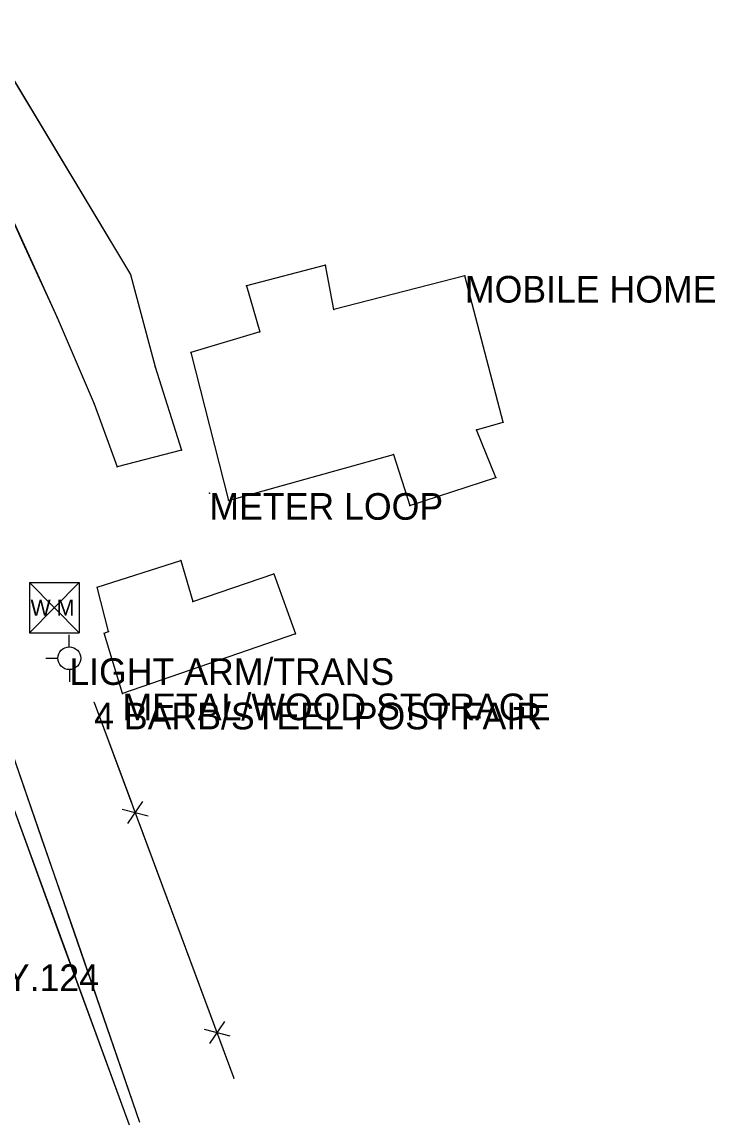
# Model space of a CAD drawing. Extents: x 1050807 to 1053552, y 395828 to 398415.
# Drawn here: x 1052790.6 to 1052920.5, y 395828.1 to 396034.9 of the extents above; entities that cross this region are included whole.
import ezdxf

# ---------------------------------------------------------------- set-up
doc = ezdxf.new("R2010")
doc.units = 0
for name, color, linetype in [('S_BREAKLINE_ANNOT', 7, 'Continuous'), ('S_BUILDING', 7, 'Continuous'), ('S_BUILDING_ANNOT', 7, 'Continuous'), ('S_DITCHLINE', 7, 'Continuous'), ('S_DRIVEWAY', 7, 'Continuous'), ('S_FENCE', 7, 'Continuous'), ('S_FENCE_ANNOT', 7, 'Continuous'), ('S_MISC_STRUCTURES_ANNOT', 7, 'Continuous'), ('S_MSC_PT_SYM', 7, 'Continuous'), ('S_RDW_PT_SYM', 7, 'Continuous'), ('S_STR_PT_SYM', 7, 'Continuous'), ('S_SURVEY_TEXT_ANNOT', 7, 'Continuous'), ('S_UTILITY_POLE', 7, 'Continuous'), ('S_UTILITY_POLE_ANNOT', 7, 'Continuous'), ('S_WATER_UTILITIES', 7, 'Continuous')]:
    doc.layers.add(name, color=color, linetype=linetype)

msp = doc.modelspace()

# ---------------------------------------------------------------- linework, layer by layer
at = {"layer": 'S_BUILDING'}
for p, q in [((1052847.48, 395989.28), (1052832.67, 395985.42)), ((1052849.07, 395980.99), (1052847.48, 395989.28)), ((1052873.63, 395987.29), (1052849.07, 395980.99)), ((1052880.8, 395959.85), (1052873.63, 395987.29)), ((1052832.67, 395985.42), (1052835.14, 395976.8)), ((1052835.14, 395976.8), (1052822.2, 395972.95)), ((1052822.2, 395972.95), (1052829.32, 395945.21)), ((1052875.79, 395958.45), (1052880.8, 395959.85)), ((1052879.42, 395949.49), (1052875.79, 395958.45)), ((1052829.32, 395945.21), (1052860.21, 395953.79)), ((1052860.21, 395953.79), (1052863.3, 395944.22)), ((1052863.3, 395944.22), (1052879.42, 395949.49)), ((1052804.69, 395928.93), (1052820.34, 395933.93)), ((1052820.34, 395933.93), (1052822.62, 395926.23)), ((1052822.62, 395926.23), (1052837.78, 395931.41)), ((1052837.78, 395931.41), (1052841.85, 395920.21)), ((1052806.78, 395920.64), (1052804.69, 395928.93)), ((1052806, 395920.32), (1052806.78, 395920.64)), ((1052809.42, 395908.99), (1052806, 395920.32)), ((1052841.85, 395920.21), (1052809.42, 395908.99))]:
    msp.add_line(p, q, dxfattribs=at)
at = {"layer": 'S_DITCHLINE'}
for p, q in [((1052788.01, 395899.83), (1052812.63, 395828.64)), ((1052784.72, 395899.06), (1052810.64, 395828.11))]:
    msp.add_line(p, q, dxfattribs=at)
for points in [[(1052667.19, 396235.17), (1052672.63, 396217.62), (1052682.66, 396199.25), (1052692.68, 396180.88), (1052699.99, 396161.78), (1052707.3, 396142.68), (1052714.61, 396123.58), (1052721.92, 396104.47), (1052727.54, 396086.32), (1052733.16, 396068.18), (1052738.78, 396050.03), (1052744.4, 396031.88), (1052749.9, 396011.56), (1052755.39, 395991.25), (1052760.89, 395970.94), (1052766.38, 395950.62), (1052770.97, 395937.73), (1052775.55, 395924.84), (1052780.13, 395911.95), (1052784.72, 395899.06), (1052791.2, 395881.32), (1052797.68, 395863.58), (1052804.16, 395845.85), (1052810.64, 395828.11)], [(1052669.02, 396235.8), (1052675.04, 396219.02), (1052684.79, 396200.32), (1052694.54, 396181.62), (1052702.2, 396162.86), (1052709.86, 396144.1), (1052717.52, 396125.35), (1052725.19, 396106.59), (1052730.68, 396088.04), (1052736.18, 396069.48), (1052741.68, 396050.93), (1052747.18, 396032.38), (1052752.87, 396012.01), (1052758.56, 395991.64), (1052764.26, 395971.28), (1052769.95, 395950.91), (1052774.46, 395938.14), (1052778.98, 395925.37), (1052783.49, 395912.6), (1052788.01, 395899.83), (1052794.16, 395882.03), (1052800.32, 395864.23), (1052806.48, 395846.43), (1052812.63, 395828.64)]]:
    msp.add_lwpolyline(points, dxfattribs=at)
at = {"layer": 'S_DRIVEWAY'}
for p, q in [((1052781.19, 396037.02), (1052810.9, 395987.58)), ((1052772.8, 396032.74), (1052797.15, 395979.49)), ((1052810.9, 395987.58), (1052815.52, 395970.22)), ((1052797.15, 395979.49), (1052804.07, 395963.29)), ((1052815.52, 395970.22), (1052820.46, 395954.63)), ((1052804.07, 395963.29), (1052808.41, 395951.52)), ((1052820.46, 395954.63), (1052808.41, 395951.52))]:
    msp.add_line(p, q, dxfattribs=at)
for points in [[(1052659.6, 396252.65), (1052670.75, 396253.48), (1052686.97, 396247.75), (1052693.36, 396241.69), (1052703.81, 396231.56), (1052710.61, 396211.53), (1052717.4, 396191.5), (1052724.49, 396172.29), (1052731.58, 396153.08), (1052738.66, 396133.87), (1052745.75, 396114.65), (1052754.61, 396095.25), (1052763.47, 396075.84), (1052772.33, 396056.43), (1052781.19, 396037.02), (1052788.62, 396024.66), (1052796.05, 396012.3), (1052803.47, 395999.94), (1052810.9, 395987.58), (1052815.52, 395970.22), (1052820.46, 395954.63), (1052808.41, 395951.52)], [(1052664.49, 396242.14), (1052673.01, 396242.35), (1052682.55, 396239.86), (1052689.21, 396234.92), (1052695.83, 396227.71), (1052702.87, 396208.25), (1052709.91, 396188.79), (1052717.31, 396169.57), (1052724.71, 396150.35), (1052732.11, 396131.13), (1052739.52, 396111.91), (1052747.84, 396092.12), (1052756.16, 396072.33), (1052764.48, 396052.53), (1052772.8, 396032.74), (1052778.89, 396019.43), (1052784.98, 396006.11), (1052791.06, 395992.8), (1052797.15, 395979.49), (1052804.07, 395963.29), (1052808.41, 395951.52)]]:
    msp.add_lwpolyline(points, dxfattribs=at)
at = {"layer": 'S_FENCE'}
for p, q in [((1052804.1, 395907.28), (1052830.3, 395836.9)), ((1052809.36, 395887.29), (1052814.2, 395886.04)), ((1052813.19, 395888.72), (1052810.36, 395884.61)), ((1052824.7, 395846.07), (1052829.54, 395844.81)), ((1052828.54, 395847.5), (1052825.71, 395843.38))]:
    msp.add_line(p, q, dxfattribs=at)
for points in [[(1052804.1, 395907.28), (1052811.08, 395888.54)], [(1052812.47, 395884.79), (1052826.43, 395847.32)], [(1052827.62, 395844.1), (1052830.3, 395836.9)]]:
    msp.add_lwpolyline(points, dxfattribs=at)
at = {"layer": 'S_MSC_PT_SYM'}
for points in [[(1052825.71, 395946.57), (1052825.71, 395946.62), (1052825.71, 395946.57), (1052825.66, 395946.57), (1052825.71, 395946.57), (1052825.71, 395946.52), (1052825.71, 395946.57), (1052825.76, 395946.57)], [(1052804.1, 395907.28), (1052804.1, 395907.33), (1052804.1, 395907.28), (1052804.05, 395907.28), (1052804.1, 395907.28), (1052804.1, 395907.23), (1052804.1, 395907.28), (1052804.15, 395907.28)], [(1052830.3, 395836.9), (1052830.3, 395836.95), (1052830.3, 395836.9), (1052830.25, 395836.9), (1052830.3, 395836.9), (1052830.3, 395836.85), (1052830.3, 395836.9), (1052830.35, 395836.9)]]:
    msp.add_lwpolyline(points, dxfattribs=at)
at = {"layer": 'S_RDW_PT_SYM'}
for points in [[(1052810.9, 395987.58), (1052810.9, 395987.63), (1052810.9, 395987.58), (1052810.85, 395987.58), (1052810.9, 395987.58), (1052810.9, 395987.53), (1052810.9, 395987.58), (1052810.95, 395987.58)], [(1052797.15, 395979.49), (1052797.15, 395979.54), (1052797.15, 395979.49), (1052797.1, 395979.49), (1052797.15, 395979.49), (1052797.15, 395979.44), (1052797.15, 395979.49), (1052797.2, 395979.49)], [(1052815.52, 395970.22), (1052815.52, 395970.27), (1052815.52, 395970.22), (1052815.47, 395970.22), (1052815.52, 395970.22), (1052815.52, 395970.17), (1052815.52, 395970.22), (1052815.57, 395970.22)], [(1052804.07, 395963.29), (1052804.07, 395963.34), (1052804.07, 395963.29), (1052804.02, 395963.29), (1052804.07, 395963.29), (1052804.07, 395963.24), (1052804.07, 395963.29), (1052804.12, 395963.29)], [(1052820.46, 395954.63), (1052820.46, 395954.68), (1052820.46, 395954.63), (1052820.41, 395954.63), (1052820.46, 395954.63), (1052820.46, 395954.58), (1052820.46, 395954.63), (1052820.51, 395954.63)], [(1052808.41, 395951.52), (1052808.41, 395951.57), (1052808.41, 395951.52), (1052808.36, 395951.52), (1052808.41, 395951.52), (1052808.41, 395951.47), (1052808.41, 395951.52), (1052808.46, 395951.52)], [(1052808.41, 395951.52), (1052808.41, 395951.57), (1052808.41, 395951.52), (1052808.36, 395951.52), (1052808.41, 395951.52), (1052808.41, 395951.47), (1052808.41, 395951.52), (1052808.46, 395951.52)]]:
    msp.add_lwpolyline(points, dxfattribs=at)
at = {"layer": 'S_STR_PT_SYM'}
for points in [[(1052847.48, 395989.28), (1052847.48, 395989.33), (1052847.48, 395989.28), (1052847.43, 395989.28), (1052847.48, 395989.28), (1052847.48, 395989.23), (1052847.48, 395989.28), (1052847.53, 395989.28)], [(1052873.63, 395987.29), (1052873.63, 395987.34), (1052873.63, 395987.29), (1052873.58, 395987.29), (1052873.63, 395987.29), (1052873.63, 395987.24), (1052873.63, 395987.29), (1052873.68, 395987.29)], [(1052832.67, 395985.42), (1052832.67, 395985.47), (1052832.67, 395985.42), (1052832.62, 395985.42), (1052832.67, 395985.42), (1052832.67, 395985.37), (1052832.67, 395985.42), (1052832.72, 395985.42)], [(1052849.07, 395980.99), (1052849.07, 395981.04), (1052849.07, 395980.99), (1052849.02, 395980.99), (1052849.07, 395980.99), (1052849.07, 395980.94), (1052849.07, 395980.99), (1052849.12, 395980.99)], [(1052835.14, 395976.8), (1052835.14, 395976.85), (1052835.14, 395976.8), (1052835.09, 395976.8), (1052835.14, 395976.8), (1052835.14, 395976.75), (1052835.14, 395976.8), (1052835.19, 395976.8)], [(1052822.2, 395972.95), (1052822.2, 395973), (1052822.2, 395972.95), (1052822.15, 395972.95), (1052822.2, 395972.95), (1052822.2, 395972.9), (1052822.2, 395972.95), (1052822.25, 395972.95)], [(1052880.8, 395959.85), (1052880.8, 395959.9), (1052880.8, 395959.85), (1052880.75, 395959.85), (1052880.8, 395959.85), (1052880.8, 395959.8), (1052880.8, 395959.85), (1052880.85, 395959.85)], [(1052875.79, 395958.45), (1052875.79, 395958.5), (1052875.79, 395958.45), (1052875.74, 395958.45), (1052875.79, 395958.45), (1052875.79, 395958.4), (1052875.79, 395958.45), (1052875.84, 395958.45)], [(1052860.21, 395953.79), (1052860.21, 395953.84), (1052860.21, 395953.79), (1052860.16, 395953.79), (1052860.21, 395953.79), (1052860.21, 395953.74), (1052860.21, 395953.79), (1052860.26, 395953.79)], [(1052879.42, 395949.49), (1052879.42, 395949.54), (1052879.42, 395949.49), (1052879.37, 395949.49), (1052879.42, 395949.49), (1052879.42, 395949.44), (1052879.42, 395949.49), (1052879.47, 395949.49)], [(1052829.32, 395945.21), (1052829.32, 395945.26), (1052829.32, 395945.21), (1052829.27, 395945.21), (1052829.32, 395945.21), (1052829.32, 395945.16), (1052829.32, 395945.21), (1052829.37, 395945.21)], [(1052863.3, 395944.22), (1052863.3, 395944.27), (1052863.3, 395944.22), (1052863.25, 395944.22), (1052863.3, 395944.22), (1052863.3, 395944.17), (1052863.3, 395944.22), (1052863.35, 395944.22)], [(1052820.34, 395933.93), (1052820.34, 395933.98), (1052820.34, 395933.93), (1052820.29, 395933.93), (1052820.34, 395933.93), (1052820.34, 395933.88), (1052820.34, 395933.93), (1052820.39, 395933.93)], [(1052837.78, 395931.41), (1052837.78, 395931.46), (1052837.78, 395931.41), (1052837.73, 395931.41), (1052837.78, 395931.41), (1052837.78, 395931.36), (1052837.78, 395931.41), (1052837.83, 395931.41)], [(1052804.69, 395928.93), (1052804.69, 395928.98), (1052804.69, 395928.93), (1052804.64, 395928.93), (1052804.69, 395928.93), (1052804.69, 395928.88), (1052804.69, 395928.93), (1052804.74, 395928.93)], [(1052822.62, 395926.23), (1052822.62, 395926.28), (1052822.62, 395926.23), (1052822.57, 395926.23), (1052822.62, 395926.23), (1052822.62, 395926.18), (1052822.62, 395926.23), (1052822.67, 395926.23)], [(1052806, 395920.32), (1052806, 395920.37), (1052806, 395920.32), (1052805.95, 395920.32), (1052806, 395920.32), (1052806, 395920.27), (1052806, 395920.32), (1052806.05, 395920.32)], [(1052806.78, 395920.64), (1052806.78, 395920.69), (1052806.78, 395920.64), (1052806.73, 395920.64), (1052806.78, 395920.64), (1052806.78, 395920.59), (1052806.78, 395920.64), (1052806.83, 395920.64)], [(1052841.85, 395920.21), (1052841.85, 395920.26), (1052841.85, 395920.21), (1052841.8, 395920.21), (1052841.85, 395920.21), (1052841.85, 395920.16), (1052841.85, 395920.21), (1052841.9, 395920.21)], [(1052809.42, 395908.99), (1052809.42, 395909.04), (1052809.42, 395908.99), (1052809.37, 395908.99), (1052809.42, 395908.99), (1052809.42, 395908.94), (1052809.42, 395908.99), (1052809.47, 395908.99)]]:
    msp.add_lwpolyline(points, dxfattribs=at)
at = {"layer": 'S_UTILITY_POLE'}
for p, q in [((1052799.43, 395917.72), (1052799.43, 395919.97)), ((1052797.34, 395915.59), (1052795.02, 395915.59)), ((1052799.51, 395911.17), (1052799.51, 395913.49))]:
    msp.add_line(p, q, dxfattribs=at)
msp.add_circle((1052799.44, 395915.61), 2.13, dxfattribs=at)
at = {"layer": 'S_WATER_UTILITIES'}
for p, q in [((1052791.96, 395929.84), (1052801.29, 395929.84)), ((1052791.96, 395929.84), (1052791.96, 395920.35)), ((1052791.96, 395929.84), (1052801.29, 395920.35)), ((1052801.29, 395929.84), (1052791.96, 395920.35)), ((1052801.29, 395929.84), (1052801.29, 395920.35)), ((1052791.96, 395920.35), (1052801.29, 395920.35))]:
    msp.add_line(p, q, dxfattribs=at)

# ---------------------------------------------------------------- texts
at = {"layer": 'S_BREAKLINE_ANNOT'}
msp.add_text('4 BARB/STEEL POST FAIR', height=5, dxfattribs=at).set_placement((1052804.1, 395902.28))
msp.add_text('4 BARB/STEEL POST FAIR', height=5, dxfattribs=at).set_placement((1052804.1, 395902.28))
at = {"layer": 'S_BUILDING_ANNOT'}
for s, p in [('MOBILE HOME', (1052873.63, 395982.29)), ('METAL/WOOD STORAGE', (1052809.42, 395903.99))]:
    msp.add_text(s, height=5, dxfattribs=at).set_placement(p)
at = {"layer": 'S_FENCE_ANNOT'}
msp.add_text('4 BARB/STEEL POST FAIR', height=5, dxfattribs=at).set_placement((1052804.1, 395902.28))
at = {"layer": 'S_MISC_STRUCTURES_ANNOT'}
msp.add_text('METER LOOP', height=5, dxfattribs=at).set_placement((1052825.71, 395941.57))
at = {"layer": 'S_SURVEY_TEXT_ANNOT'}
msp.add_text('HWY.124', height=5, dxfattribs=at).set_placement((1052776.39, 395853.21))
at = {"layer": 'S_UTILITY_POLE_ANNOT'}
msp.add_text('LIGHT ARM/TRANS', height=5, dxfattribs=at).set_placement((1052799.44, 395910.61))
at = {"layer": 'S_WATER_UTILITIES'}
msp.add_text('W M', height=3, dxfattribs=at).set_placement((1052792.16, 395923.61))

doc.saveas('drawing.dxf')
